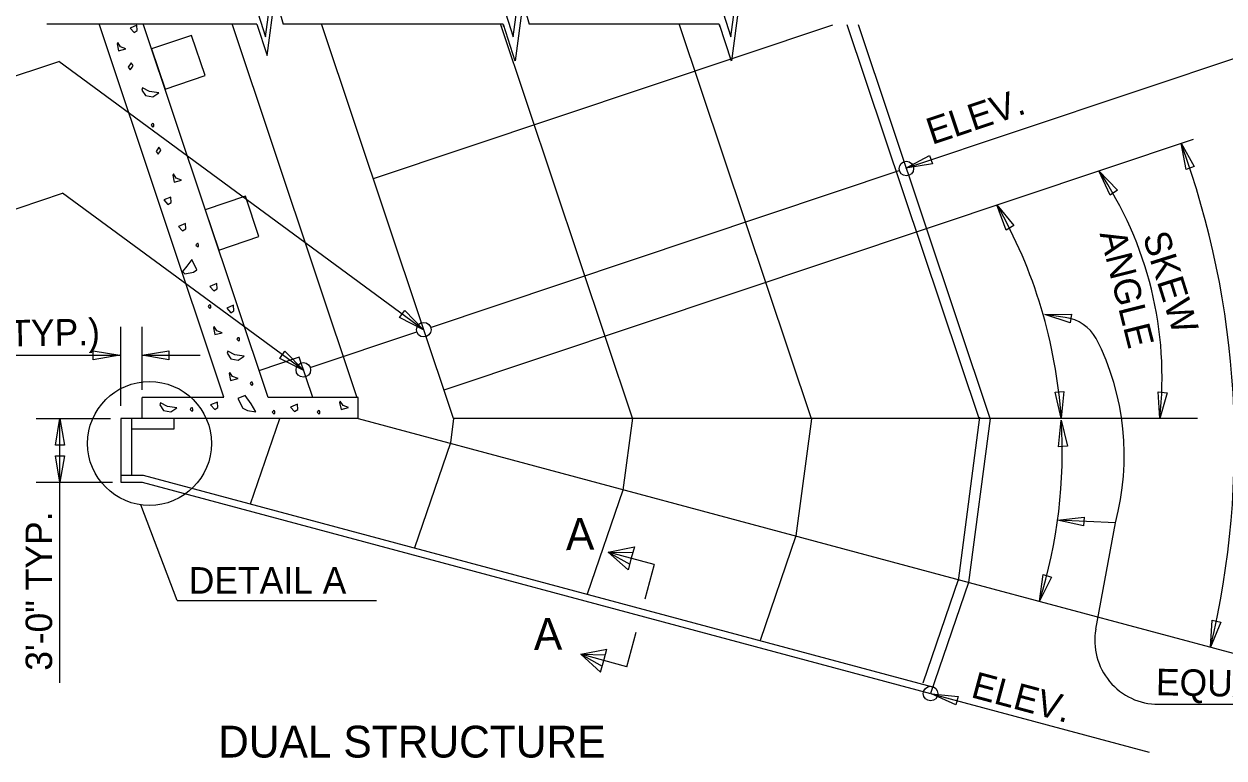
# Model space of a CAD drawing. Extents: x 0 to 272, y 0 to 188.
# Drawn here: x 50.2 to 106.8, y 44.4 to 79 of the extents above; entities that cross this region are included whole.
import ezdxf

# ---------------------------------------------------------------- set-up
doc = ezdxf.new("R2010")
doc.units = 0
for name, color, linetype in [('BRDG_ANNO_General-Notes', 7, 'Continuous'), ('BRDG_BASE_Hidden-Line', 7, 'Continuous'), ('BRDG_BASE_Obj-Line', 7, 'Continuous'), ('BRDG_BASE_Pattern', 7, 'Continuous')]:
    doc.layers.add(name, color=color, linetype=linetype)

msp = doc.modelspace()

# ---------------------------------------------------------------- linework, layer by layer
at = {"layer": 'BRDG_ANNO_General-Notes'}
for p, q in [((91.788, 72.211), (107.871, 77.592)), ((27.736, 69.191), (51.823, 77.251)), ((69.038, 64.594), (51.823, 77.251)), ((92.809, 69.389), (105.354, 73.587)), ((105, 72.145), (104.764, 73.39)), ((104.764, 73.39), (105.391, 72.288)), ((91.788, 72.211), (92.907, 72.805)), ((92.907, 72.805), (93.039, 72.41)), ((69.361, 64.707), (91.468, 72.104)), ((93.039, 72.41), (91.788, 72.211)), ((101.416, 70.94), (100.888, 72.093)), ((100.888, 72.093), (101.761, 71.174)), ((105.391, 72.288), (105, 72.145)), ((29.335, 63.443), (52.01, 71.029)), ((63.381, 62.669), (52.01, 71.029)), ((101.761, 71.174), (101.416, 70.94)), ((96.52, 69.296), (96.083, 70.485)), ((96.083, 70.485), (96.882, 69.502)), ((96.882, 69.502), (96.52, 69.296)), ((67.907, 65.166), (68.154, 65.502)), ((69.038, 64.594), (67.907, 65.166)), ((68.154, 65.502), (69.038, 64.594)), ((98.335, 65.315), (99.602, 65.334)), ((99.307, 65.168), (98.335, 65.315)), ((99.539, 64.922), (98.335, 65.315)), ((99.602, 65.334), (99.539, 64.922)), ((54.762, 61.009), (54.762, 64.732)), ((55.762, 61.766), (55.762, 64.732)), ((63.685, 62.808), (68.717, 64.492)), ((53.456, 63.181), (53.456, 63.598)), ((53.456, 63.598), (54.706, 63.39)), ((55.762, 63.39), (57.012, 63.598)), ((57.012, 63.598), (57.012, 63.181)), ((62.25, 63.241), (62.497, 63.577)), ((62.497, 63.577), (63.381, 62.669)), ((45.029, 63.39), (54.706, 63.39)), ((54.706, 63.39), (53.456, 63.181)), ((55.762, 63.39), (58.502, 63.39)), ((57.012, 63.181), (55.762, 63.39)), ((63.381, 62.669), (62.25, 63.241)), ((98.82, 61.654), (99.236, 61.682)), ((99.112, 60.421), (98.82, 61.654)), ((99.236, 61.682), (99.112, 60.421)), ((103.693, 61.668), (104.107, 61.621)), ((103.759, 60.402), (103.693, 61.668)), ((104.107, 61.621), (103.759, 60.402)), ((50.757, 60.402), (54.273, 60.402)), ((51.674, 59.152), (51.883, 60.402)), ((51.883, 60.402), (52.091, 59.152)), ((51.883, 57.402), (51.883, 60.402)), ((105.546, 60.402), (95.762, 60.402)), ((98.988, 59.076), (99.117, 60.337)), ((99.117, 60.337), (99.404, 59.102)), ((52.091, 59.152), (51.674, 59.152)), ((99.404, 59.102), (98.988, 59.076)), ((51.674, 58.652), (52.091, 58.652)), ((51.883, 57.402), (51.674, 58.652)), ((52.091, 58.652), (51.883, 57.402)), ((50.757, 57.402), (54.359, 57.402)), ((51.883, 47.95), (51.883, 57.402)), ((57.41, 51.833), (55.691, 56.337)), ((98.93, 55.606), (100.188, 55.759)), ((98.93, 55.606), (100.188, 55.759)), ((101.671, 55.486), (98.93, 55.606)), ((100.17, 55.343), (98.93, 55.606)), ((100.17, 55.343), (98.93, 55.606)), ((100.188, 55.759), (100.17, 55.343)), ((100.188, 55.759), (100.17, 55.343)), ((100.748, 50.472), (101.671, 55.486)), ((77.748, 54.111), (78.982, 54.357)), ((78.982, 54.357), (78.833, 53.814)), ((79.919, 53.517), (77.748, 54.111)), ((77.748, 54.111), (78.685, 53.272)), ((77.748, 54.111), (78.759, 53.543)), ((77.748, 54.111), (78.908, 54.086)), ((78.833, 53.814), (78.685, 53.272)), ((79.919, 53.517), (79.474, 51.89)), ((94.769, 52.679), (107.458, 49.279)), ((98.081, 51.791), (98.257, 53.046)), ((98.655, 52.921), (98.081, 51.791)), ((98.257, 53.046), (98.655, 52.921)), ((57.41, 51.833), (66.822, 51.833)), ((106.15, 49.629), (106.239, 50.893)), ((106.644, 50.796), (106.15, 49.629)), ((106.239, 50.893), (106.644, 50.796)), ((78.618, 48.697), (79.063, 50.325)), ((76.448, 49.291), (77.681, 49.537)), ((78.618, 48.697), (76.448, 49.291)), ((76.448, 49.291), (77.384, 48.452)), ((76.448, 49.291), (77.607, 49.265)), ((76.448, 49.291), (77.459, 48.723)), ((77.533, 48.994), (77.681, 49.537)), ((77.384, 48.452), (77.533, 48.994)), ((92.987, 47.427), (103.268, 44.673)), ((94.141, 46.902), (92.987, 47.427)), ((92.987, 47.427), (94.249, 47.305)), ((94.249, 47.305), (94.141, 46.902)), ((103.698, 46.929), (116.724, 46.929))]:
    msp.add_line(p, q, dxfattribs=at)
for centre, radius in [((91.81, 72.195), 0.343), ((69.045, 64.596), 0.343), ((63.365, 62.701), 0.343), ((56.107, 59.23), 2.923), ((92.95, 47.437), 0.343)]:
    msp.add_circle(centre, radius, dxfattribs=at)
for centre, radius, start, end in [((66.213, 59.221), 41.073, 346.4946, 20.1789), ((86.483, 62.357), 17.387, 353.5439, 34.0519), ((75.648, 58.847), 23.517, 3.8375, 29.6609), ((99.031, 63.187), 2, 29.8249, 82.0723), ((89.876, 58.655), 12.213, 344.963, 26.9061), ((75.648, 58.847), 23.517, 342.5402, 3.6309), ((103.698, 49.929), 3, 169.5711, 270)]:
    msp.add_arc(centre, radius, start, end, dxfattribs=at)
at = {"layer": 'BRDG_BASE_Hidden-Line'}
for p, q in [((65.906, 61.388), (60.025, 78.965)), ((95.235, 60.401), (89.023, 78.965)), ((55.262, 60.402), (55.262, 59.893)), ((57.262, 60.402), (57.262, 59.902)), ((95.266, 60.467), (94.25, 52.747)), ((57.262, 59.902), (55.262, 59.902)), ((55.262, 59.902), (55.262, 57.735)), ((94.272, 52.844), (92.587, 47.921))]:
    msp.add_line(p, q, dxfattribs=at)
at = {"layer": 'BRDG_BASE_Obj-Line'}
for p, q in [((61.578, 78.4), (61.953, 81.206)), ((73.265, 78.4), (73.637, 81.205)), ((83.532, 78.402), (83.904, 81.207)), ((61.1, 79.88), (61.578, 78.4)), ((61.654, 77.529), (62.029, 80.336)), ((62.029, 80.336), (62.407, 79.009)), ((72.784, 79.879), (73.265, 78.4)), ((73.377, 77.281), (73.736, 79.988)), ((73.736, 79.988), (74.016, 79.01)), ((83.052, 79.881), (83.532, 78.402)), ((83.577, 77.281), (83.936, 79.99)), ((61.176, 79.009), (51.259, 79.009)), ((59.619, 61.409), (53.744, 78.965)), ((61.704, 61.402), (55.827, 78.965)), ((61.704, 61.402), (55.827, 78.965)), ((61.176, 79.009), (61.654, 77.529)), ((63.231, 79.009), (62.407, 79.009)), ((68.628, 79.009), (63.231, 79.009)), ((70.454, 60.402), (64.243, 78.965)), ((66.679, 71.719), (88.337, 78.965)), ((72.784, 79.009), (68.628, 79.009)), ((78.884, 60.42), (72.679, 78.965)), ((72.782, 78.965), (72.804, 78.897)), ((72.784, 79.009), (73.346, 77.281)), ((72.804, 78.897), (72.813, 78.965)), ((82.984, 79.011), (74.016, 79.01)), ((87.33, 60.39), (81.115, 78.965)), ((82.983, 78.965), (83.004, 78.899)), ((82.984, 79.011), (83.546, 77.281)), ((83.004, 78.899), (83.013, 78.965)), ((95.762, 60.402), (89.55, 78.965)), ((90.114, 77.281), (89.55, 78.965)), ((58.093, 78.474), (56.198, 77.833)), ((58.734, 76.579), (58.093, 78.474)), ((56.198, 77.833), (56.84, 75.938)), ((56.84, 75.938), (58.734, 76.579)), ((60.631, 70.886), (58.736, 70.245)), ((61.272, 68.992), (60.631, 70.886)), ((58.736, 70.245), (59.378, 68.35)), ((70.011, 61.761), (92.809, 69.389)), ((59.378, 68.35), (61.272, 68.992)), ((63.165, 63.299), (61.271, 62.658)), ((63.806, 61.404), (63.165, 63.299)), ((59.619, 61.402), (55.762, 61.402)), ((55.762, 60.402), (55.762, 61.402)), ((65.947, 61.402), (61.704, 61.402)), ((65.947, 60.402), (65.947, 61.402)), ((65.947, 60.402), (54.762, 60.402)), ((54.762, 60.402), (54.762, 57.402)), ((62.239, 60.398), (60.862, 56.376)), ((65.947, 60.402), (94.769, 52.679)), ((70.454, 60.402), (70.303, 59.254)), ((95.762, 60.402), (70.454, 60.402)), ((95.762, 60.402), (70.454, 60.402)), ((78.884, 60.42), (78.437, 57.028)), ((87.33, 60.39), (86.596, 54.872)), ((95.762, 60.402), (94.745, 52.682)), ((70.303, 59.254), (68.609, 54.304)), ((54.762, 57.735), (55.806, 57.735)), ((54.762, 57.402), (55.762, 57.402)), ((55.762, 57.402), (92.95, 47.437)), ((55.806, 57.735), (93.036, 47.759)), ((78.437, 57.028), (76.757, 52.121)), ((86.596, 54.872), (84.907, 49.937)), ((94.745, 52.682), (92.95, 47.437))]:
    msp.add_line(p, q, dxfattribs=at)
at = {"layer": 'BRDG_BASE_Pattern'}
for points in [[(55.189, 78.823), (55.38, 78.612), (55.53, 78.706), (55.512, 78.959)], [(54.578, 78.079), (54.644, 77.752), (54.996, 77.84), (54.738, 77.939), (54.607, 78.136)], [(55.104, 76.977), (55.198, 76.846), (55.31, 76.996), (55.329, 77.052), (55.236, 77.183)], [(55.753, 75.892), (55.923, 75.639), (56.27, 75.574), (56.551, 75.761), (56.115, 75.823), (55.778, 76)], [(56.182, 74.238), (56.253, 74.168), (56.309, 74.177), (56.309, 74.196), (56.309, 74.252), (56.289, 74.308), (56.257, 74.313), (56.229, 74.303), (56.219, 74.295), (56.207, 74.271)], [(56.417, 73.004), (56.511, 72.873), (56.623, 73.023), (56.642, 73.08), (56.549, 73.21)], [(57.204, 71.885), (57.27, 71.557), (57.622, 71.645), (57.364, 71.744), (57.233, 71.941)], [(56.788, 70.715), (56.979, 70.504), (57.129, 70.598), (57.111, 70.851)], [(57.476, 69.463), (57.667, 69.253), (57.817, 69.347), (57.799, 69.6)], [(58.298, 68.583), (58.369, 68.512), (58.424, 68.521), (58.424, 68.54), (58.424, 68.596), (58.405, 68.653), (58.373, 68.657), (58.345, 68.648), (58.335, 68.639), (58.322, 68.615)], [(57.864, 67.584), (57.657, 67.34), (57.769, 67.228), (58.182, 67.303), (58.333, 67.416), (58.108, 67.903)], [(58.957, 66.635), (59.148, 66.425), (59.298, 66.519), (59.28, 66.772)], [(58.87, 65.688), (58.941, 65.617), (58.997, 65.626), (58.997, 65.645), (58.997, 65.701), (58.977, 65.757), (58.945, 65.762), (58.917, 65.752), (58.907, 65.744), (58.895, 65.72)], [(59.748, 65.608), (59.939, 65.398), (60.089, 65.492), (60.071, 65.745)], [(59.123, 64.69), (59.188, 64.363), (59.541, 64.451), (59.282, 64.55), (59.152, 64.747)], [(60.228, 64.145), (60.299, 64.074), (60.355, 64.083), (60.355, 64.102), (60.355, 64.158), (60.335, 64.214), (60.303, 64.219), (60.275, 64.209), (60.265, 64.201), (60.253, 64.177)], [(59.773, 63.483), (59.943, 63.229), (60.29, 63.165), (60.571, 63.351), (60.135, 63.413), (59.797, 63.59)], [(59.866, 62.526), (59.932, 62.198), (60.284, 62.287), (60.025, 62.385), (59.895, 62.582)], [(60.85, 62.052), (60.92, 61.981), (60.976, 61.99), (60.976, 62.009), (60.976, 62.065), (60.957, 62.122), (60.925, 62.126), (60.897, 62.116), (60.887, 62.108), (60.874, 62.084)], [(56.595, 61.045), (56.765, 60.792), (57.112, 60.727), (57.393, 60.914), (56.956, 60.976), (56.619, 61.152)], [(58.991, 61.046), (59.182, 60.836), (59.332, 60.93), (59.314, 61.183)], [(60.279, 61.347), (60.505, 60.895), (60.73, 60.783), (61.124, 60.728), (60.899, 61.103), (60.618, 61.497)], [(65.075, 61.163), (65.141, 60.836), (65.493, 60.924), (65.235, 61.023), (65.104, 61.22)], [(58.024, 60.839), (58.095, 60.768), (58.15, 60.777), (58.15, 60.796), (58.15, 60.852), (58.131, 60.908), (58.099, 60.913), (58.071, 60.903), (58.061, 60.895), (58.048, 60.871)], [(61.896, 60.704), (61.966, 60.633), (62.022, 60.642), (62.022, 60.661), (62.022, 60.717), (62.003, 60.774), (61.971, 60.778), (61.943, 60.769), (61.933, 60.76), (61.92, 60.736)], [(62.761, 60.945), (62.953, 60.735), (63.102, 60.829), (63.085, 61.082)], [(64.017, 60.704), (64.087, 60.633), (64.143, 60.642), (64.143, 60.661), (64.143, 60.717), (64.124, 60.774), (64.092, 60.778), (64.064, 60.769), (64.054, 60.76), (64.041, 60.736)]]:
    msp.add_lwpolyline(points, close=True, dxfattribs=at)

# ---------------------------------------------------------------- texts
at = {"layer": 'BRDG_ANNO_General-Notes'}
for s, height, rotation, p in [('ELEV.', 1.25, 18.4999, (93.016, 73.308)), ('ANGLE', 1.25, 284.1001, (100.918, 69.132)), ('SKEW', 1.25, 287.4001, (102.946, 69.007)), ('SKEW', 1.25, 287.4001, (102.946, 69.007)), ('1\'-0" (TYP.)', 1.25, 1.1, (45.159, 63.714)), ('3\'-0" TYP.', 1.25, 90, (51.513, 48.513)), ('A', 1.5, 1.1, (75.756, 54.198)), ('A', 1.5, 1.1, (74.24, 49.487)), ('ELEV.', 1.25, 345, (94.805, 47.277)), ('EQUAL ANGLES', 1.25, 358.9, (103.571, 47.361))]:
    msp.add_text(s, height=height, rotation=rotation, dxfattribs=at).set_placement(p)
for s, height, p in [('DETAIL A', 1.25, (57.96, 52.149)), ('DUAL STRUCTURE', 1.5, (59.344, 44.42))]:
    msp.add_text(s, height=height, dxfattribs=at).set_placement(p)

doc.saveas('drawing.dxf')
